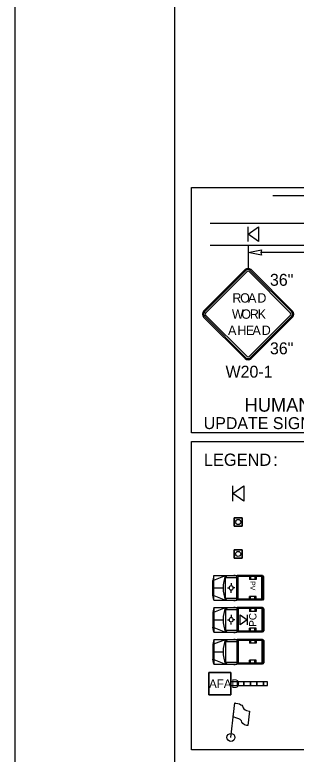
# Model space of a CAD drawing. Extents: x 99999.1 to 100095.7, y 99995 to 100010.7.
# Drawn here: x 99999.062 to 100000.714, y 100001.151 to 100005.492 of the extents above; entities that cross this region are included whole.
import ezdxf

# ---------------------------------------------------------------- set-up
doc = ezdxf.new("R2010")
doc.units = 0
for name, color, linetype in [('RD_ED_ShoulderPavedEdge', 7, 'Continuous'), ('RD_MK_LineEdgeWhite', 7, 'Continuous'), ('SH_DE_DetailHeading2Text', 7, 'Continuous'), ('SH_GI_PlotLimits', 7, 'Continuous'), ('SH_GI_SheetBorder', 7, 'Continuous'), ('TR_SN_ConstructionSigns', 7, 'Continuous'), ('TR_WZ_AFAD', 7, 'Continuous'), ('TR_WZ_FlaggingStation', 7, 'Continuous'), ('TR_WZ_MotoristVehicle', 7, 'Continuous'), ('TR_WZ_PortableSignMountBlk-Org', 7, 'Continuous'), ('TR_WZ_PortableSignMountBlk-Wht', 7, 'Continuous'), ('TR_WZ_ProtectiveVehicle', 7, 'Continuous'), ('TR_WZ_TrafficCone', 7, 'Continuous'), ('TR_WZ_WorkZoneDetails', 7, 'Continuous'), ('TR_WZ_WorkZoneTextCurrent', 7, 'Continuous')]:
    doc.layers.add(name, color=color, linetype=linetype)

msp = doc.modelspace()

# ---------------------------------------------------------------- linework, layer by layer
at = {"layer": 'RD_ED_ShoulderPavedEdge'}
msp.add_line((100000.2089, 100004.1394), (100003.1825, 100004.1394), dxfattribs=at)
at = {"layer": 'RD_MK_LineEdgeWhite'}
msp.add_line((100000.2089, 100004.2685), (100003.1825, 100004.2685), dxfattribs=at)
at = {"layer": 'SH_GI_PlotLimits'}
msp.add_lwpolyline([(99999.0625, 99999.6875), (100016.0625, 99999.6875), (100016.0625, 100010.6875), (99999.0625, 100010.6875)], close=True, dxfattribs=at)
at = {"layer": 'SH_GI_SheetBorder'}
msp.add_line((100000, 100010.375), (100000, 100000), dxfattribs=at)
at = {"layer": 'TR_SN_ConstructionSigns'}
for p, q in [((100000.4143, 100003.996), (100000.1706, 100003.7524)), ((100000.4191, 100003.9912), (100000.1755, 100003.7476)), ((100000.1822, 100003.7408), (100000.4259, 100003.9844)), ((100000.4375, 100003.9844), (100000.6811, 100003.7408)), ((100000.6879, 100003.7476), (100000.4442, 100003.9912)), ((100000.6927, 100003.7524), (100000.4491, 100003.996)), ((100000.1706, 100003.7176), (100000.4143, 100003.474)), ((100000.1755, 100003.7224), (100000.4191, 100003.4788)), ((100000.4259, 100003.4856), (100000.1822, 100003.7292)), ((100000.6811, 100003.7292), (100000.4375, 100003.4856)), ((100000.4442, 100003.4788), (100000.6879, 100003.7224)), ((100000.4491, 100003.474), (100000.6927, 100003.7176))]:
    msp.add_line(p, q, dxfattribs=at)
for centre, radius, start, end in [((100000.4317, 100003.9786), 0.0246, 45, 135), ((100000.4317, 100003.9786), 0.0178, 45, 135), ((100000.4317, 100003.9786), 0.0082, 45, 135), ((100000.188, 100003.735), 0.0246, 135, 225), ((100000.188, 100003.735), 0.0178, 135, 225), ((100000.6753, 100003.735), 0.0178, 315, 45), ((100000.6753, 100003.735), 0.0246, 315, 45), ((100000.188, 100003.735), 0.0082, 135, 225), ((100000.6753, 100003.735), 0.0082, 315, 45), ((100000.4317, 100003.4914), 0.0082, 225, 315), ((100000.4317, 100003.4914), 0.0246, 225, 315), ((100000.4317, 100003.4914), 0.0178, 225, 315)]:
    msp.add_arc(centre, radius, start, end, dxfattribs=at)
at = {"layer": 'TR_WZ_AFAD'}
for p, q in [((100000.2009, 100001.5003), (100000.2009, 100001.6299)), ((100000.2009, 100001.6299), (100000.3305, 100001.6299)), ((100000.3305, 100001.6299), (100000.2009, 100001.6299)), ((100000.2009, 100001.6299), (100000.2009, 100001.5003)), ((100000.3305, 100001.6299), (100000.3305, 100001.5003)), ((100000.3305, 100001.5699), (100000.3305, 100001.6299)), ((100000.3689, 100001.5759), (100000.3305, 100001.5759)), ((100000.3305, 100001.5759), (100000.3305, 100001.5699)), ((100000.4073, 100001.5759), (100000.3689, 100001.5759)), ((100000.4457, 100001.5759), (100000.4073, 100001.5759)), ((100000.4073, 100001.5651), (100000.4073, 100001.5759)), ((100000.4841, 100001.5759), (100000.4457, 100001.5759)), ((100000.4457, 100001.5759), (100000.4457, 100001.5651)), ((100000.5225, 100001.5759), (100000.4841, 100001.5759)), ((100000.4841, 100001.5651), (100000.4841, 100001.5759)), ((100000.5225, 100001.5759), (100000.5225, 100001.5651)), ((100000.3305, 100001.5699), (100000.3305, 100001.5651)), ((100000.3689, 100001.5543), (100000.4073, 100001.5543)), ((100000.4073, 100001.5543), (100000.4073, 100001.5651)), ((100000.4073, 100001.5543), (100000.4457, 100001.5543)), ((100000.4457, 100001.5651), (100000.4457, 100001.5543)), ((100000.4457, 100001.5543), (100000.4841, 100001.5543)), ((100000.4841, 100001.5543), (100000.4841, 100001.5651)), ((100000.4841, 100001.5543), (100000.5225, 100001.5543)), ((100000.5225, 100001.5651), (100000.5225, 100001.5543)), ((100000.5225, 100001.5543), (100000.5465, 100001.5543)), ((100000.3305, 100001.5003), (100000.2009, 100001.5003)), ((100000.2009, 100001.5003), (100000.3305, 100001.5003))]:
    msp.add_line(p, q, dxfattribs=at)
for points in [[(100000.3305, 100001.5543), (100000.5465, 100001.5543), (100000.5465, 100001.5759), (100000.3305, 100001.5759)], [(100000.3689, 100001.5543), (100000.3689, 100001.5651), (100000.3689, 100001.5759)], [(100000.3689, 100001.5759), (100000.3689, 100001.5651), (100000.3689, 100001.5543)], [(100000.4073, 100001.5759), (100000.4073, 100001.5651), (100000.4073, 100001.5543)], [(100000.4457, 100001.5543), (100000.4457, 100001.5651), (100000.4457, 100001.5759)], [(100000.4841, 100001.5759), (100000.4841, 100001.5651), (100000.4841, 100001.5543)], [(100000.5225, 100001.5543), (100000.5225, 100001.5651), (100000.5225, 100001.5759)], [(100000.5465, 100001.5543), (100000.5465, 100001.5759), (100000.5225, 100001.5759)], [(100000.3305, 100001.5003), (100000.3305, 100001.5603), (100000.3305, 100001.5699)], [(100000.3305, 100001.5651), (100000.3305, 100001.5603), (100000.3305, 100001.5543), (100000.3689, 100001.5543)]]:
    msp.add_lwpolyline(points, dxfattribs=at)
at = {"layer": 'TR_WZ_FlaggingStation'}
for p, q in [((100000.3314, 100001.2497), (100000.3545, 100001.452)), ((100000.3451, 100001.3699), (100000.3545, 100001.4522)), ((100000.4394, 100001.4034), (100000.4299, 100001.319)), ((100000.3451, 100001.3699), (100000.3451, 100001.3699))]:
    msp.add_line(p, q, dxfattribs=at)
for points in [[(100000.3545, 100001.4522), (100000.3586, 100001.4513), (100000.3715, 100001.4488), (100000.3814, 100001.4458), (100000.3884, 100001.4414), (100000.3945, 100001.438), (100000.3986, 100001.4331), (100000.4017, 100001.4275), (100000.4021, 100001.423), (100000.4059, 100001.4164), (100000.4137, 100001.411), (100000.4226, 100001.4073), (100000.4394, 100001.4034)], [(100000.4299, 100001.319), (100000.424, 100001.32), (100000.4112, 100001.3234), (100000.4, 100001.3309), (100000.3953, 100001.3385), (100000.3925, 100001.3459), (100000.3859, 100001.3538), (100000.378, 100001.3583), (100000.3655, 100001.3634), (100000.3451, 100001.3699)]]:
    msp.add_lwpolyline(points, dxfattribs=at)
msp.add_circle((100000.3314, 100001.2497), 0.0234, dxfattribs=at)
at = {"layer": 'TR_WZ_MotoristVehicle'}
for p, q in [((100000.2305, 100002.012), (100000.2239, 100001.9829)), ((100000.2305, 100002.012), (100000.2305, 100001.868)), ((100000.2305, 100002.012), (100000.3665, 100002.012)), ((100000.2305, 100001.9856), (100000.2985, 100002.012)), ((100000.2985, 100002.012), (100000.2985, 100001.868)), ((100000.2998, 100002.012), (100000.2998, 100001.868)), ((100000.2998, 100002.012), (100000.3084, 100002.0008)), ((100000.348, 100002.014), (100000.3562, 100002.014)), ((100000.3665, 100002.012), (100000.3665, 100001.868)), ((100000.5166, 100002.012), (100000.3685, 100002.012)), ((100000.3685, 100002.012), (100000.3685, 100001.868)), ((100000.5124, 100002.0062), (100000.3727, 100002.0062)), ((100000.3727, 100002.0062), (100000.3727, 100001.8737)), ((100000.4395, 100002.0062), (100000.4395, 100001.9897)), ((100000.4467, 100002.0062), (100000.4467, 100001.9897)), ((100000.4711, 100002.0062), (100000.4711, 100001.9897)), ((100000.4791, 100002.0062), (100000.4791, 100001.9897)), ((100000.5124, 100002.0062), (100000.5124, 100001.8737)), ((100000.5166, 100002.012), (100000.5166, 100001.868)), ((100000.5204, 100002.0096), (100000.5171, 100002.0096)), ((100000.5171, 100002.0096), (100000.5171, 100001.8704)), ((100000.2239, 100001.9829), (100000.2239, 100001.8971)), ((100000.2998, 100002.0008), (100000.3665, 100002.0008)), ((100000.3324, 100001.9685), (100000.3324, 100001.9569)), ((100000.4791, 100001.9897), (100000.4395, 100001.9897)), ((100000.5236, 100002.0052), (100000.5236, 100001.8747)), ((100000.2305, 100001.94), (100000.2852, 100001.94)), ((100000.3107, 100001.9401), (100000.3198, 100001.94)), ((100000.3329, 100001.9123), (100000.3327, 100001.9231)), ((100000.3426, 100001.9397), (100000.3426, 100001.9397)), ((100000.3546, 100001.9394), (100000.3439, 100001.9397)), ((100000.5236, 100001.9501), (100000.5171, 100001.9474)), ((100000.5236, 100001.9298), (100000.5171, 100001.9325)), ((100000.5218, 100001.94), (100000.5189, 100001.94)), ((100000.5204, 100001.942), (100000.5204, 100001.938)), ((100000.2305, 100001.868), (100000.2239, 100001.8971)), ((100000.2305, 100001.8944), (100000.2985, 100001.868)), ((100000.2998, 100001.8791), (100000.3665, 100001.8791)), ((100000.3069, 100001.8791), (100000.2998, 100001.868)), ((100000.4395, 100001.8737), (100000.4395, 100001.8903)), ((100000.4791, 100001.8903), (100000.4395, 100001.8903)), ((100000.4467, 100001.8737), (100000.4467, 100001.8903)), ((100000.4711, 100001.8737), (100000.4711, 100001.8903)), ((100000.4791, 100001.8737), (100000.4791, 100001.8903)), ((100000.2305, 100001.868), (100000.3665, 100001.868)), ((100000.348, 100001.866), (100000.3562, 100001.866)), ((100000.5166, 100001.868), (100000.3685, 100001.868)), ((100000.5124, 100001.8737), (100000.3727, 100001.8737)), ((100000.5204, 100001.8704), (100000.5171, 100001.8704)), ((100000.2305, 100001.8245), (100000.2239, 100001.7955)), ((100000.2239, 100001.7955), (100000.2239, 100001.7096)), ((100000.2305, 100001.8245), (100000.2305, 100001.6805)), ((100000.2305, 100001.8245), (100000.3665, 100001.8245)), ((100000.2305, 100001.7982), (100000.2985, 100001.8245)), ((100000.2985, 100001.8245), (100000.2985, 100001.6805)), ((100000.2998, 100001.8245), (100000.2998, 100001.6805)), ((100000.2998, 100001.8245), (100000.3084, 100001.8134)), ((100000.2998, 100001.8134), (100000.3665, 100001.8134)), ((100000.348, 100001.8266), (100000.3562, 100001.8266)), ((100000.3665, 100001.8245), (100000.3665, 100001.6805)), ((100000.5166, 100001.8245), (100000.3685, 100001.8245)), ((100000.3685, 100001.8245), (100000.3685, 100001.6805)), ((100000.5124, 100001.8188), (100000.3727, 100001.8188)), ((100000.3727, 100001.8188), (100000.3727, 100001.6863)), ((100000.4395, 100001.8188), (100000.4395, 100001.8022)), ((100000.4791, 100001.8022), (100000.4395, 100001.8022)), ((100000.4467, 100001.8188), (100000.4467, 100001.8022)), ((100000.4711, 100001.8188), (100000.4711, 100001.8022)), ((100000.4791, 100001.8188), (100000.4791, 100001.8022)), ((100000.5124, 100001.8188), (100000.5124, 100001.6863)), ((100000.5166, 100001.8245), (100000.5166, 100001.6805)), ((100000.5204, 100001.8222), (100000.5171, 100001.8222)), ((100000.5171, 100001.8222), (100000.5171, 100001.6829)), ((100000.5236, 100001.8178), (100000.5236, 100001.6873)), ((100000.2305, 100001.7525), (100000.2852, 100001.7525)), ((100000.5236, 100001.7627), (100000.5171, 100001.76)), ((100000.5218, 100001.7525), (100000.5189, 100001.7525)), ((100000.5204, 100001.7546), (100000.5204, 100001.7505)), ((100000.2305, 100001.6805), (100000.2239, 100001.7096)), ((100000.2305, 100001.7069), (100000.2985, 100001.6805)), ((100000.4395, 100001.6863), (100000.4395, 100001.7028)), ((100000.4791, 100001.7028), (100000.4395, 100001.7028)), ((100000.4467, 100001.6863), (100000.4467, 100001.7028)), ((100000.4711, 100001.6863), (100000.4711, 100001.7028)), ((100000.4791, 100001.6863), (100000.4791, 100001.7028)), ((100000.5236, 100001.7424), (100000.5171, 100001.7451)), ((100000.2305, 100001.6805), (100000.3665, 100001.6805)), ((100000.2998, 100001.6917), (100000.3665, 100001.6917)), ((100000.3069, 100001.6917), (100000.2998, 100001.6805)), ((100000.348, 100001.6785), (100000.3562, 100001.6785)), ((100000.5166, 100001.6805), (100000.3685, 100001.6805)), ((100000.5124, 100001.6863), (100000.3727, 100001.6863)), ((100000.5204, 100001.6829), (100000.5171, 100001.6829))]:
    msp.add_line(p, q, dxfattribs=at)
for centre, major_axis, start_param, end_param in [((100000.3957, 100001.94), (0, -0.1511), 4.215667, 5.208926), ((100000.5204, 100002.0052), (0, 0.00439), 4.712389, 6.283185), ((100000.5204, 100001.8747), (0, -0.00439), 0, 1.570796), ((100000.3957, 100001.7525), (0, -0.1511), 4.215667, 5.208926), ((100000.5204, 100001.8178), (0, 0.00439), 4.712389, 6.283185), ((100000.5204, 100001.6873), (0, -0.00439), 0, 1.570796)]:
    msp.add_ellipse(centre, major_axis=major_axis, ratio=0.73155, start_param=start_param, end_param=end_param, dxfattribs=at)
for centre, major_axis in [((100000.3324, 100001.94), (0, 0.0139)), ((100000.5204, 100001.94), (0, 0.00203)), ((100000.5204, 100001.7525), (0, 0.00203))]:
    msp.add_ellipse(centre, major_axis=major_axis, ratio=0.73155, dxfattribs=at)
at = {"layer": 'TR_WZ_PortableSignMountBlk-Org'}
for p, q in [((100000.4317, 100004.1609), (100000.4317, 100004.247)), ((100000.3414, 100002.6372), (100000.3414, 100002.7272))]:
    msp.add_line(p, q, dxfattribs=at)
for points in [[(100000.4317, 100004.2039), (100000.4935, 100004.247), (100000.4935, 100004.1609)], [(100000.3414, 100002.6821), (100000.406, 100002.7272), (100000.406, 100002.6372)]]:
    msp.add_lwpolyline(points, close=True, dxfattribs=at)
at = {"layer": 'TR_WZ_PortableSignMountBlk-Wht'}
msp.add_line((100000.4259, 100001.9687), (100000.4259, 100001.9111), dxfattribs=at)
msp.add_lwpolyline([(100000.4259, 100001.94), (100000.3845, 100001.9111), (100000.3845, 100001.9687)], close=True, dxfattribs=at)
at = {"layer": 'TR_WZ_ProtectiveVehicle'}
for p, q in [((100000.2305, 100002.1994), (100000.2239, 100002.1704)), ((100000.2305, 100002.0554), (100000.2305, 100002.1994)), ((100000.2305, 100002.1994), (100000.3665, 100002.1994)), ((100000.2305, 100002.1731), (100000.2985, 100002.1994)), ((100000.2985, 100002.0554), (100000.2985, 100002.1994)), ((100000.2998, 100002.0554), (100000.2998, 100002.1994)), ((100000.3069, 100002.1883), (100000.2998, 100002.1994)), ((100000.2998, 100002.1883), (100000.3665, 100002.1883)), ((100000.348, 100002.2015), (100000.3562, 100002.2015)), ((100000.3665, 100002.0554), (100000.3665, 100002.1994)), ((100000.5166, 100002.1994), (100000.3685, 100002.1994)), ((100000.3685, 100002.0554), (100000.3685, 100002.1994)), ((100000.5124, 100002.1937), (100000.3727, 100002.1937)), ((100000.3727, 100002.0612), (100000.3727, 100002.1937)), ((100000.4395, 100002.1937), (100000.4395, 100002.1771)), ((100000.4467, 100002.1937), (100000.4467, 100002.1771)), ((100000.4711, 100002.1937), (100000.4711, 100002.1771)), ((100000.4791, 100002.1937), (100000.4791, 100002.1771)), ((100000.5124, 100002.0612), (100000.5124, 100002.1937)), ((100000.5166, 100002.0554), (100000.5166, 100002.1994)), ((100000.5204, 100002.1971), (100000.5171, 100002.1971)), ((100000.5171, 100002.0578), (100000.5171, 100002.1971)), ((100000.5236, 100002.0622), (100000.5236, 100002.1927)), ((100000.2239, 100002.0845), (100000.2239, 100002.1704)), ((100000.3329, 100002.1551), (100000.3327, 100002.1443)), ((100000.4791, 100002.1771), (100000.4395, 100002.1771)), ((100000.5236, 100002.1376), (100000.5171, 100002.1349)), ((100000.2305, 100002.1274), (100000.2852, 100002.1274)), ((100000.3107, 100002.1273), (100000.3198, 100002.1274)), ((100000.3324, 100002.0989), (100000.3324, 100002.1105)), ((100000.3426, 100002.1277), (100000.3426, 100002.1277)), ((100000.3546, 100002.128), (100000.3439, 100002.1277)), ((100000.5236, 100002.1173), (100000.5171, 100002.12)), ((100000.5218, 100002.1274), (100000.5189, 100002.1274)), ((100000.5204, 100002.1254), (100000.5204, 100002.1295)), ((100000.2305, 100002.0554), (100000.2239, 100002.0845)), ((100000.2305, 100002.0818), (100000.2985, 100002.0554)), ((100000.2305, 100002.0554), (100000.3665, 100002.0554)), ((100000.2998, 100002.0554), (100000.3084, 100002.0666)), ((100000.2998, 100002.0666), (100000.3665, 100002.0666)), ((100000.348, 100002.0534), (100000.3562, 100002.0534)), ((100000.5166, 100002.0554), (100000.3685, 100002.0554)), ((100000.5124, 100002.0612), (100000.3727, 100002.0612)), ((100000.4791, 100002.0777), (100000.4395, 100002.0777)), ((100000.4395, 100002.0612), (100000.4395, 100002.0777)), ((100000.4467, 100002.0612), (100000.4467, 100002.0777)), ((100000.4711, 100002.0612), (100000.4711, 100002.0777)), ((100000.4791, 100002.0612), (100000.4791, 100002.0777)), ((100000.5204, 100002.0578), (100000.5171, 100002.0578))]:
    msp.add_line(p, q, dxfattribs=at)
for centre, major_axis, start_param, end_param in [((100000.3957, 100002.1275), (0, -0.1511), 4.215852, 5.209111), ((100000.5204, 100002.1927), (0, 0.00439), 4.712389, 6.283185), ((100000.5204, 100002.0622), (0, -0.00439), 6.283185, 7.853982)]:
    msp.add_ellipse(centre, major_axis=major_axis, ratio=0.73155, start_param=start_param, end_param=end_param, dxfattribs=at)
for centre, major_axis in [((100000.3324, 100002.1274), (0, 0.0139)), ((100000.5204, 100002.1274), (0, 0.00203))]:
    msp.add_ellipse(centre, major_axis=major_axis, ratio=0.73155, dxfattribs=at)
at = {"layer": 'TR_WZ_TrafficCone'}
for points in [[(100000.3497, 100002.5383), (100000.3977, 100002.5383), (100000.3977, 100002.4903), (100000.3497, 100002.4903), (100000.3497, 100002.5383)], [(100000.3497, 100002.4903), (100000.3977, 100002.4903), (100000.3977, 100002.5383), (100000.3497, 100002.5383), (100000.3497, 100002.4903)], [(100000.3497, 100002.3508), (100000.3977, 100002.3508), (100000.3977, 100002.3028), (100000.3497, 100002.3028), (100000.3497, 100002.3508)], [(100000.3497, 100002.3028), (100000.3977, 100002.3028), (100000.3977, 100002.3508), (100000.3497, 100002.3508), (100000.3497, 100002.3028)]]:
    msp.add_lwpolyline(points, dxfattribs=at)
for centre in [(100000.3737, 100002.5143), (100000.3737, 100002.3268)]:
    msp.add_circle(centre, 0.015, dxfattribs=at)
at = {"layer": 'TR_WZ_WorkZoneDetails'}
for p, q in [((100000.7726, 100004.4292), (100000.578, 100004.4292)), ((100000.4317, 100004.1396), (100000.4317, 100004.0032)), ((100001.0019, 100004.0963), (100000.5073, 100004.0963))]:
    msp.add_line(p, q, dxfattribs=at)
msp.add_lwpolyline([(100000.4317, 100004.0963), (100000.511, 100004.1119), (100000.5073, 100004.0963), (100000.511, 100004.0807)], close=True, dxfattribs=at)
at = {"layer": 'TR_WZ_WorkZoneTextCurrent'}
for points in [[(100000.1, 100004.4792), (100003.2886, 100004.4792), (100003.2886, 100003.0379), (100000.1, 100003.0379)], [(100000.1, 100002.9879), (100003.2886, 100002.9879), (100003.2886, 100001.1759), (100000.1, 100001.1759)]]:
    msp.add_lwpolyline(points, close=True, dxfattribs=at)

# ---------------------------------------------------------------- texts
at = {"layer": 'SH_DE_DetailHeading2Text'}
msp.add_text('HUMAN FLAGGER SUBSTITUTION', height=0.08, rotation=360, dxfattribs=at).set_placement((100000.4115, 100003.1619))
at = {"layer": 'TR_SN_ConstructionSigns'}
for s, p in [('36"', (100000.5601, 100003.9011)), ('36"', (100000.5601, 100003.4989)), ('W20-1', (100000.2996, 100003.3618))]:
    msp.add_text(s, height=0.07, rotation=360, dxfattribs=at).set_placement(p)
for s, p in [('R', (100000.3397, 100003.8026)), ('O', (100000.3854, 100003.8026)), ('A', (100000.4315, 100003.8026)), ('D', (100000.4864, 100003.8026)), ('W', (100000.3369, 100003.7077)), ('O', (100000.3922, 100003.7077)), ('R', (100000.4423, 100003.7077)), ('K', (100000.4882, 100003.7077)), ('A', (100000.3141, 100003.6127)), ('H', (100000.3688, 100003.6127)), ('E', (100000.4191, 100003.6127)), ('A', (100000.4574, 100003.6127)), ('D', (100000.5121, 100003.6127))]:
    msp.add_text(s, height=0.0547, dxfattribs=at).set_placement(p)
at = {"layer": 'TR_WZ_AFAD'}
msp.add_text('AFAD', height=0.0504, dxfattribs=at).set_placement((100000.203, 100001.5399))
at = {"layer": 'TR_WZ_MotoristVehicle'}
msp.add_text('PC', height=0.0432, rotation=90, dxfattribs=at).set_placement((100000.4809, 100001.8996))
at = {"layer": 'TR_WZ_ProtectiveVehicle'}
msp.add_text('PV', height=0.03006, rotation=270, dxfattribs=at).set_placement((100000.4442, 100002.1682))
at = {"layer": 'TR_WZ_WorkZoneTextCurrent'}
msp.add_text('UPDATE SIGNAGE & USE STOP/SLOW PADDLE', height=0.07, dxfattribs=at).set_placement((100000.1713, 100003.0599))
for s, p in [('LEGEND', (100000.172, 100002.8439)), (':', (100000.5795, 100002.8439))]:
    msp.add_text(s, height=0.072, rotation=360, dxfattribs=at).set_placement(p)

doc.saveas('drawing.dxf')
